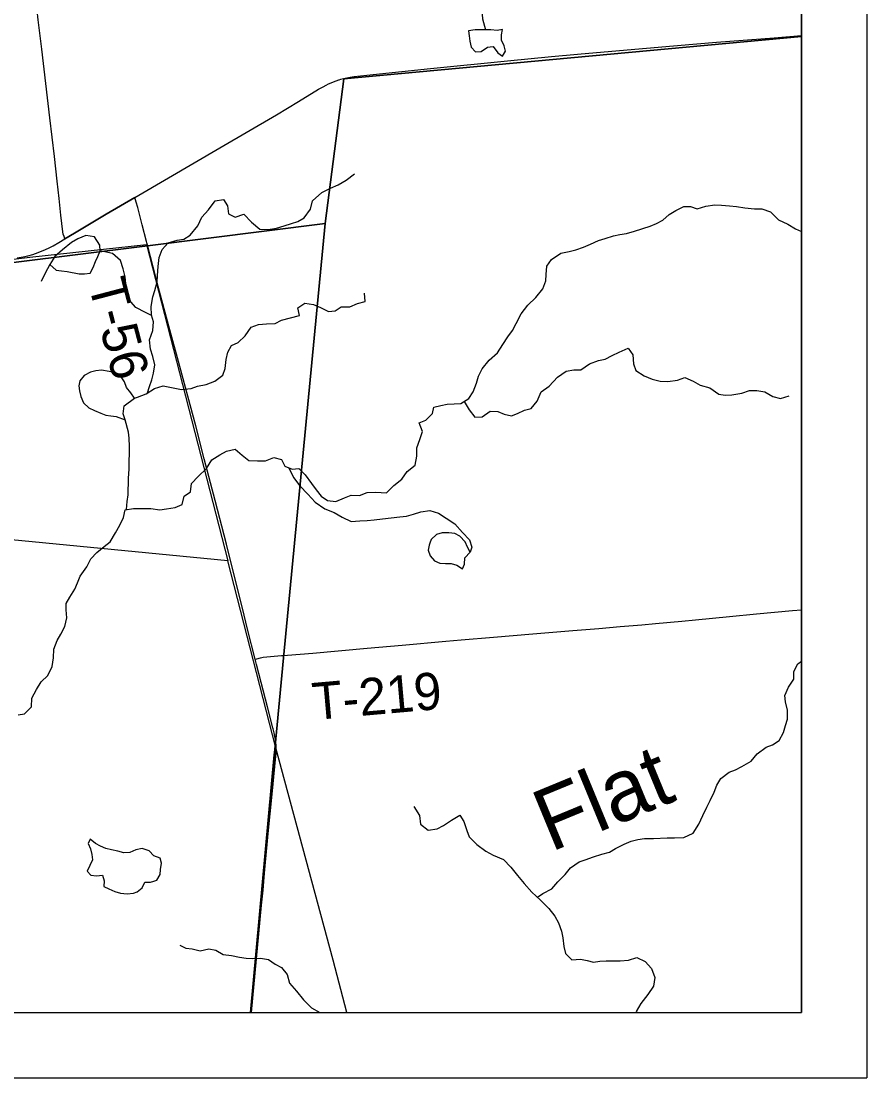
# Model space of a CAD drawing. Extents: x 0 to 34, y -5.4 to 22.
# Drawn here: x 7.705 to 9, y 14 to 15.618 of the extents above; entities that cross this region are included whole.
import ezdxf

# ---------------------------------------------------------------- set-up
doc = ezdxf.new("R2010")
doc.units = 0
for name, color, linetype in [('Default', 7, 'Continuous'), ('GM_X_County_Road', 7, 'Continuous'), ('GM_X_Minor_Lake', 7, 'Continuous'), ('GM_X_Minor_River', 7, 'Continuous'), ('GM_X_Minor_River_Text', 7, 'Continuous'), ('GM_X_Rail_Line', 7, 'Continuous'), ('GM_X_Section', 7, 'Continuous'), ('GM_X_Township_Road', 7, 'Continuous'), ('GM_X_Township_Road_Text', 7, 'Continuous'), ('SH_Data', 7, 'Continuous')]:
    doc.layers.add(name, color=color, linetype=linetype)

msp = doc.modelspace()

# ---------------------------------------------------------------- linework, layer by layer
at = {"layer": 'Default'}
for points in [[(7.0382, 14.1), (8.0569, 14.1), (8.0946, 14.5055), (8.0215, 14.7918), (7.1062, 14.8804)], [(8.0569, 14.1), (8.2036, 14.1), (8.1825, 14.1804), (8.0946, 14.5055)]]:
    msp.add_lwpolyline(points, close=True, dxfattribs=at)
at = {"layer": 'GM_X_County_Road'}
for points in [[(8.1911, 15.528), (8.1917, 15.5282), (8.1946, 15.529), (8.1987, 15.53), (8.2036, 15.5311), (8.2085, 15.5322), (8.215, 15.533), (8.2439, 15.536), (8.3316, 15.5452), (8.4494, 15.5571), (8.5168, 15.5637), (8.5567, 15.5672), (8.633, 15.5742), (8.7334, 15.5828), (8.7695, 15.5856), (8.8581, 15.5925), (8.9, 15.596)], [(7.8787, 15.348), (7.9305, 15.378), (8.0091, 15.4241), (8.096, 15.4745), (8.1296, 15.4946), (8.1604, 15.5136), (8.1674, 15.5175), (8.1717, 15.5199), (8.1755, 15.5218), (8.1795, 15.5236), (8.183, 15.5252), (8.187, 15.5265), (8.1911, 15.528)], [(7.7718, 15.2845), (7.7866, 15.2932), (7.8349, 15.3221), (7.8787, 15.348)], [(7.732, 15.264), (7.7385, 15.2666), (7.7465, 15.2703), (7.7538, 15.2741), (7.7624, 15.2789), (7.7718, 15.2845)], [(7.6989, 15.2557), (7.7077, 15.2571), (7.7152, 15.2586), (7.7228, 15.2607), (7.7307, 15.2635), (7.732, 15.264)]]:
    msp.add_lwpolyline(points, dxfattribs=at)
at = {"layer": 'GM_X_Minor_Lake'}
for points in [[(8.4158, 15.6045), (8.4003, 15.6044), (8.39, 15.603), (8.3907, 15.5954), (8.3921, 15.587), (8.3942, 15.5779), (8.4005, 15.5709), (8.4093, 15.5716), (8.4188, 15.5779), (8.4233, 15.5784)], [(8.4233, 15.5784), (8.4276, 15.5789), (8.435, 15.5696), (8.4418, 15.5642), (8.4464, 15.5717), (8.4443, 15.5801), (8.4406, 15.5889), (8.4404, 15.5969), (8.442, 15.6052), (8.4336, 15.6038), (8.4242, 15.6047), (8.4158, 15.6045)], [(7.8256, 15.266), (7.8254, 15.2751), (7.8169, 15.2874), (7.8041, 15.2895), (7.7915, 15.2848), (7.782, 15.2792), (7.7681, 15.2677), (7.7562, 15.2573), (7.7488, 15.2453)], [(7.7488, 15.2453), (7.7585, 15.2367), (7.7668, 15.2355), (7.7755, 15.2346), (7.7936, 15.2312), (7.8016, 15.2311), (7.8103, 15.2321), (7.815, 15.2408), (7.8185, 15.2498), (7.8224, 15.2577), (7.8256, 15.266)], [(7.8786, 15.0406), (7.8727, 15.0489), (7.8664, 15.057), (7.8631, 15.0654), (7.8568, 15.0746), (7.8478, 15.0801), (7.8395, 15.0817), (7.8277, 15.0834), (7.819, 15.0824), (7.811, 15.0803), (7.8011, 15.0755), (7.7945, 15.0672), (7.7933, 15.0597), (7.7943, 15.0517), (7.796, 15.0433), (7.8004, 15.0334), (7.8087, 15.026), (7.8173, 15.0217), (7.8267, 15.0178), (7.8346, 15.0146), (7.8422, 15.0137), (7.8501, 15.0128), (7.8642, 15.0073)], [(7.8642, 15.0073), (7.8612, 15.0166), (7.8625, 15.0287), (7.8786, 15.0406)], [(8.3923, 14.8047), (8.3882, 14.8127), (8.3849, 14.8207), (8.3767, 14.8292), (8.3688, 14.8335), (8.3597, 14.8344), (8.3495, 14.8342), (8.3408, 14.8317), (8.3327, 14.8242), (8.3307, 14.8187)], [(8.3307, 14.8187), (8.3295, 14.8155), (8.3283, 14.808), (8.3312, 14.7992), (8.3379, 14.7915), (8.3462, 14.7879), (8.3549, 14.7874), (8.3636, 14.7877), (8.3719, 14.7849), (8.3805, 14.7791), (8.384, 14.7866), (8.3842, 14.7961), (8.3923, 14.8047)], [(7.9078, 14.3011), (7.9124, 14.3025), (7.9178, 14.3111), (7.918, 14.3191), (7.92, 14.3285), (7.9175, 14.3365), (7.9081, 14.3397), (7.901, 14.3474), (7.89, 14.351), (7.8802, 14.3489), (7.8714, 14.3452), (7.8619, 14.3446), (7.8528, 14.3471), (7.8434, 14.3491), (7.8343, 14.3511), (7.8264, 14.3547), (7.8189, 14.359), (7.8107, 14.3652), (7.8075, 14.3588), (7.8112, 14.3504), (7.813, 14.342), (7.814, 14.334)], [(7.814, 14.334), (7.8061, 14.3163), (7.8117, 14.3101), (7.8204, 14.3092), (7.8295, 14.3102), (7.8321, 14.3018), (7.8316, 14.2931), (7.8391, 14.2892), (7.8481, 14.2853), (7.8572, 14.2825), (7.8674, 14.2819), (7.8769, 14.2829), (7.8826, 14.2847), (7.8899, 14.2907), (7.8942, 14.2997), (7.9029, 14.2996), (7.9078, 14.3011)]]:
    msp.add_lwpolyline(points, dxfattribs=at)
at = {"layer": 'GM_X_Minor_River'}
for points in [[(8.3922, 15.6544), (8.3989, 15.6438), (8.4104, 15.6341), (8.4113, 15.6212), (8.4158, 15.6045)], [(7.8983, 15.0489), (7.9012, 15.0583), (7.9052, 15.0685), (7.9073, 15.0787), (7.9094, 15.0916), (7.9066, 15.1045), (7.903, 15.1156), (7.9013, 15.13), (7.9065, 15.144), (7.9074, 15.1576), (7.9042, 15.1675), (7.9041, 15.1812), (7.9066, 15.1959), (7.9098, 15.2057), (7.913, 15.2186), (7.9136, 15.2284), (7.9149, 15.2424), (7.9163, 15.2561), (7.921, 15.2681), (7.9299, 15.2786), (7.9436, 15.2825), (7.9542, 15.2843), (7.9638, 15.2902), (7.9754, 15.3044), (7.9817, 15.3179), (7.9917, 15.3291), (8.0018, 15.3426), (8.0147, 15.3447), (8.0209, 15.3351), (8.0226, 15.3229), (8.0324, 15.3178), (8.0457, 15.3221), (8.0576, 15.3102), (8.0703, 15.2993), (8.0831, 15.2987), (8.0957, 15.3008), (8.1078, 15.3044), (8.1189, 15.308), (8.1284, 15.3109), (8.1383, 15.3168), (8.148, 15.3299), (8.1512, 15.3427), (8.1651, 15.3554), (8.1788, 15.3623), (8.1903, 15.3671), (8.2025, 15.3744), (8.2155, 15.3841)], [(8.3367, 15.027), (8.3473, 15.0295), (8.3572, 15.0312), (8.3682, 15.0318), (8.378, 15.0323), (8.3903, 15.0401), (8.3969, 15.0502), (8.402, 15.0634), (8.4052, 15.0744), (8.4107, 15.0853), (8.4215, 15.0987), (8.4342, 15.1099), (8.4427, 15.123), (8.4501, 15.1343), (8.4571, 15.144), (8.463, 15.1549), (8.4708, 15.1696), (8.4808, 15.1831), (8.4928, 15.195), (8.504, 15.2081), (8.5083, 15.2201), (8.5089, 15.23), (8.5098, 15.2425), (8.5172, 15.253), (8.5314, 15.2626), (8.5439, 15.2654), (8.5542, 15.2679), (8.566, 15.2719), (8.5766, 15.2766), (8.5892, 15.2821), (8.5991, 15.2853), (8.612, 15.2893), (8.6215, 15.291), (8.6318, 15.2927), (8.6443, 15.2963), (8.6683, 15.3039), (8.6778, 15.3083), (8.6874, 15.3134), (8.6974, 15.3216), (8.7073, 15.3282), (8.7199, 15.3341), (8.7301, 15.3343), (8.7403, 15.3307), (8.7532, 15.3347), (8.7672, 15.3367), (8.7775, 15.3361), (8.7895, 15.3352), (8.8001, 15.3342), (8.813, 15.3321), (8.8277, 15.3307), (8.839, 15.3305), (8.8526, 15.3261), (8.8649, 15.3138), (8.8788, 15.3071), (8.8908, 15.3001), (8.9, 15.2957)], [(7.9043, 15.1672), (7.8952, 15.1719), (7.8802, 15.1793), (7.8694, 15.1924), (7.8666, 15.2027), (7.8653, 15.2156), (7.8639, 15.2263), (7.8611, 15.2384), (7.8572, 15.2514), (7.8449, 15.2622), (7.8256, 15.266), (7.8254, 15.2751), (7.8169, 15.2874), (7.8041, 15.2895), (7.7915, 15.2848), (7.782, 15.2792), (7.7681, 15.2677), (7.7562, 15.2573), (7.7488, 15.2453), (7.7418, 15.2321), (7.7355, 15.2193)], [(7.8664, 14.8701), (7.8673, 14.8826), (7.8686, 14.8928), (7.869, 14.9178), (7.87, 14.9322), (7.8702, 14.9451), (7.8707, 14.9549), (7.8706, 14.9667), (7.8704, 14.9792), (7.869, 14.9887), (7.8642, 15.0073), (7.8612, 15.0166), (7.8625, 15.0287), (7.8786, 15.0406), (7.8832, 15.042), (7.8961, 15.0474), (7.9088, 15.0556), (7.9221, 15.0595), (7.9353, 15.057), (7.9504, 15.0537), (7.9651, 15.0554), (7.975, 15.059), (7.988, 15.0618), (8.0013, 15.0669), (8.0136, 15.0761), (8.0171, 15.0863), (8.0189, 15.0996), (8.0213, 15.1113), (8.0268, 15.1211), (8.0371, 15.1258), (8.0479, 15.1359), (8.0572, 15.1494), (8.0682, 15.1533), (8.0807, 15.1543), (8.094, 15.1552), (8.1035, 15.1603), (8.1172, 15.1635), (8.1309, 15.1671), (8.1288, 15.1789), (8.1395, 15.1863), (8.1527, 15.1841), (8.1633, 15.1794), (8.1757, 15.1735), (8.1855, 15.1741), (8.1951, 15.1804), (8.2083, 15.1805), (8.2201, 15.1856), (8.2319, 15.1885), (8.2306, 15.2014)], [(8.3832, 15.0356), (8.3907, 15.0226), (8.3996, 15.0115), (8.4106, 15.0121), (8.4229, 15.0206), (8.435, 15.0204), (8.4447, 15.016), (8.4557, 15.0136), (8.4652, 15.0172), (8.4759, 15.0223), (8.4857, 15.0248), (8.495, 15.036), (8.5013, 15.0503), (8.5136, 15.0592), (8.5263, 15.0727), (8.5393, 15.0819), (8.5511, 15.084), (8.5617, 15.0838), (8.5751, 15.0934), (8.5892, 15.0985), (8.599, 15.1002), (8.6097, 15.1061), (8.6204, 15.1113), (8.6345, 15.1171), (8.6415, 15.1071), (8.6424, 15.093), (8.6464, 15.0831), (8.6588, 15.0746), (8.6712, 15.0698), (8.6832, 15.0669), (8.6953, 15.066), (8.7098, 15.0684), (8.7212, 15.0724), (8.734, 15.0668), (8.7448, 15.0606), (8.7595, 15.0565), (8.7734, 15.0468), (8.7832, 15.0451), (8.7934, 15.0457), (8.8086, 15.0481), (8.8204, 15.0524), (8.8313, 15.0523), (8.8438, 15.0501), (8.8558, 15.0431), (8.8678, 15.0399), (8.8812, 15.0442)], [(7.7005, 14.5558), (7.71, 14.5572), (7.7208, 14.568), (7.721, 14.5813), (7.7281, 14.5948), (7.7355, 14.6061), (7.7458, 14.6161), (7.7521, 14.63), (7.7546, 14.6433), (7.7548, 14.6565), (7.76, 14.6697), (7.7658, 14.6795), (7.7717, 14.6912), (7.7746, 14.7044), (7.7736, 14.7165), (7.7738, 14.726), (7.7796, 14.7361), (7.787, 14.7482), (7.791, 14.758), (7.7953, 14.7681), (7.8054, 14.7824), (7.8117, 14.7944), (7.8205, 14.8045), (7.8317, 14.8134), (7.8412, 14.8208), (7.8494, 14.8347), (7.8557, 14.8463), (7.8615, 14.858), (7.864, 14.8697), (7.8769, 14.8718), (7.8898, 14.8716), (7.9034, 14.8717), (7.9174, 14.8696), (7.9276, 14.8713), (7.9409, 14.8733), (7.9516, 14.8777), (7.9544, 14.8905), (7.964, 14.8972), (7.9657, 14.9101), (7.9761, 14.9209), (7.9888, 14.9332), (7.9966, 14.946), (8.0092, 14.9541), (8.0195, 14.9596), (8.0328, 14.9628), (8.0433, 14.9535), (8.0537, 14.9454), (8.067, 14.9448), (8.0791, 14.9449), (8.0917, 14.9496), (8.1033, 14.9468), (8.1085, 14.9365), (8.1201, 14.9321), (8.13, 14.9331), (8.14, 14.923), (8.1497, 14.91), (8.1567, 14.9004), (8.1645, 14.8904), (8.1742, 14.8837), (8.1867, 14.8824), (8.2, 14.8882), (8.2103, 14.8919), (8.2228, 14.8916), (8.2346, 14.8964), (8.2482, 14.8969), (8.2645, 14.8959), (8.2756, 14.9067), (8.2879, 14.9167), (8.296, 14.9283), (8.3083, 14.9383), (8.3108, 14.952), (8.311, 14.9645), (8.3154, 14.9773), (8.3194, 14.9897), (8.3143, 15.0027), (8.3246, 15.0067), (8.3346, 15.0172), (8.3367, 15.027)], [(8.115, 14.934), (8.1218, 14.9192), (8.1318, 14.9065), (8.1437, 14.8938), (8.1552, 14.8814), (8.1698, 14.8713), (8.1841, 14.8654), (8.1965, 14.8583), (8.2104, 14.852), (8.2236, 14.8526), (8.2346, 14.8535), (8.2452, 14.8541), (8.2581, 14.8558), (8.2714, 14.8574), (8.285, 14.8587), (8.2949, 14.8601), (8.3059, 14.8629), (8.3169, 14.8665), (8.3306, 14.8685), (8.3438, 14.8645), (8.3558, 14.8567), (8.3692, 14.8482), (8.3808, 14.8351), (8.3912, 14.8235), (8.3948, 14.8123), (8.3923, 14.8047)], [(8.4954, 14.2766), (8.5035, 14.2823), (8.5177, 14.2896), (8.5265, 14.3001), (8.5377, 14.3113), (8.5462, 14.3217), (8.5592, 14.3306), (8.5687, 14.3339), (8.5813, 14.3386), (8.5942, 14.3425), (8.6056, 14.3457), (8.6152, 14.3513), (8.6285, 14.3579), (8.6388, 14.3622), (8.6491, 14.3651), (8.6597, 14.3664), (8.673, 14.3666), (8.6942, 14.3677), (8.7055, 14.3676), (8.7195, 14.3681), (8.734, 14.3746), (8.7426, 14.3882), (8.7489, 14.4017), (8.7551, 14.4145), (8.7599, 14.4246), (8.7661, 14.4374), (8.7701, 14.448), (8.7763, 14.4581), (8.7893, 14.4678), (8.7989, 14.4714), (8.8084, 14.4765), (8.8226, 14.485), (8.8318, 14.4962), (8.8456, 14.5062), (8.8555, 14.5099), (8.8658, 14.5165), (8.8721, 14.5289), (8.8753, 14.5395), (8.8785, 14.5493), (8.8787, 14.5629), (8.8752, 14.5759), (8.8742, 14.5854), (8.8801, 14.5982), (8.8879, 14.6102), (8.8884, 14.6223), (8.8943, 14.634), (8.9, 14.6378)], [(8.3063, 14.4154), (8.3148, 14.4019), (8.3165, 14.3886), (8.3281, 14.3793), (8.3417, 14.381), (8.3516, 14.3861), (8.3639, 14.3946), (8.3765, 14.402), (8.3828, 14.3924), (8.3875, 14.3787), (8.3907, 14.3692), (8.4026, 14.3572), (8.4164, 14.3471), (8.4277, 14.3408), (8.4435, 14.3341), (8.455, 14.3225), (8.465, 14.3099), (8.4754, 14.2975), (8.4869, 14.2844), (8.5003, 14.2721), (8.513, 14.2593), (8.5222, 14.2474), (8.5277, 14.2371), (8.5325, 14.2245), (8.5342, 14.2146), (8.5358, 14.2009), (8.5383, 14.1903), (8.5484, 14.1806), (8.5613, 14.1819), (8.5714, 14.1798), (8.5812, 14.177), (8.5911, 14.1787), (8.6009, 14.1793), (8.6221, 14.179), (8.635, 14.1803), (8.6476, 14.1842), (8.6607, 14.1783), (8.67, 14.1672), (8.6754, 14.1538), (8.6733, 14.1405), (8.6644, 14.1274), (8.6536, 14.114), (8.6466, 14.1016), (8.6477, 14.1)], [(7.9476, 14.2031), (7.9568, 14.1987), (7.9666, 14.1974), (7.979, 14.1942), (7.9923, 14.1974), (8.0029, 14.1957), (8.0141, 14.1886), (8.027, 14.1873), (8.0394, 14.1848), (8.0492, 14.1831), (8.0591, 14.1829), (8.0712, 14.1831), (8.0837, 14.181), (8.0938, 14.174), (8.1035, 14.1689), (8.1124, 14.1581), (8.116, 14.1448), (8.1267, 14.1329), (8.1371, 14.1194), (8.1494, 14.1071), (8.1623, 14.1)]]:
    msp.add_lwpolyline(points, dxfattribs=at)
at = {"layer": 'GM_X_Rail_Line'}
msp.add_lwpolyline([(4.0439, 14.8538), (4.7395, 14.9295), (4.8765, 14.9444), (6.1164, 15.0793), (6.4403, 15.1171), (6.4463, 15.1177), (6.92, 15.1674), (6.9294, 15.1684), (6.9348, 15.169), (6.9914, 15.1749), (7.0389, 15.1799), (7.3134, 15.2082), (7.6796, 15.247), (7.6929, 15.2483), (7.8942, 15.2734), (7.8983, 15.2739), (8.1702, 15.3079), (8.1991, 15.5295), (8.9, 15.5944), (8.9, 19.2127)], dxfattribs=at)
for points in [[(8.0559, 14.1), (8.9, 14.1), (8.9, 15.5944), (8.1991, 15.5295), (8.1702, 15.3079), (8.1066, 14.6429), (8.0933, 14.5029), (8.0925, 14.4946)], [(2.9527, 14.1), (8.0559, 14.1), (8.0925, 14.4946), (8.0933, 14.5029), (8.1066, 14.6429), (8.1702, 15.3079), (7.8983, 15.2739), (7.8942, 15.2734), (7.6929, 15.2483), (7.6796, 15.247), (7.3134, 15.2082), (7.0389, 15.1799), (6.9914, 15.1749), (6.9348, 15.169), (6.9294, 15.1684), (6.92, 15.1674), (6.4463, 15.1177), (6.4403, 15.1171), (6.1164, 15.0793), (4.8765, 14.9444), (4.7395, 14.9295), (4.0439, 14.8538), (3.0059, 14.7462), (2.9641, 14.2324)]]:
    msp.add_lwpolyline(points, close=True, dxfattribs=at)
at = {"layer": 'GM_X_Section'}
msp.add_lwpolyline([(7.7181, 15.2564), (7.8967, 15.2761), (8.0215, 14.7918), (7.1062, 14.8804), (7.1421, 15.1859)], close=True, dxfattribs=at)
at = {"layer": 'GM_X_Township_Road'}
for p, q in [((7.8974, 15.2786), (7.8969, 15.2805)), ((8.1065, 14.6467), (8.1125, 14.6472))]:
    msp.add_line(p, q, dxfattribs=at)
for points in [[(7.7718, 15.2845), (7.7706, 15.2881), (7.7693, 15.2918), (7.7686, 15.2952), (7.7658, 15.321), (7.763, 15.3464), (7.7601, 15.3729), (7.7558, 15.4106), (7.7489, 15.4699), (7.7366, 15.575), (7.7311, 15.6198), (7.7294, 15.6344), (7.728, 15.6469), (7.7268, 15.6591), (7.7258, 15.6691), (7.7214, 15.707), (7.7198, 15.722)], [(7.8787, 15.348), (7.8349, 15.3221), (7.7866, 15.2932), (7.7718, 15.2845)], [(7.8969, 15.2805), (7.8902, 15.3062), (7.8834, 15.3326), (7.8809, 15.3409), (7.8787, 15.348)], [(8.0903, 14.5359), (8.0819, 14.5681), (8.0724, 14.6055), (8.0654, 14.6326), (8.0633, 14.6409), (8.0517, 14.6868), (8.0438, 14.7193), (8.0267, 14.7881), (8.0193, 14.8169), (8.0019, 14.8837), (7.985, 14.9477), (7.9721, 14.9985), (7.9441, 15.1023), (7.9324, 15.1455), (7.9146, 15.2114), (7.8988, 15.273), (7.8974, 15.2786)], [(8.1125, 14.6472), (8.1515, 14.6504), (8.2346, 14.658), (8.2884, 14.6626), (8.3552, 14.6684), (8.3789, 14.6706), (8.4281, 14.6748), (8.4886, 14.6799), (8.5497, 14.685), (8.5897, 14.6881), (8.6224, 14.6908), (8.6553, 14.6937), (8.6764, 14.6955), (8.7165, 14.6994), (8.7375, 14.7013), (8.7898, 14.7063), (8.831, 14.7104), (8.8863, 14.7154), (8.9, 14.7168)], [(8.0633, 14.6409), (8.0656, 14.6415), (8.0714, 14.6431), (8.0756, 14.6439), (8.081, 14.6446), (8.1035, 14.6464), (8.1065, 14.6467)], [(8.0933, 14.4767), (8.0952, 14.4973), (8.0954, 14.502), (8.0954, 14.5053), (8.0953, 14.5096), (8.0949, 14.5133), (8.0942, 14.5182), (8.0935, 14.5224), (8.0921, 14.5282), (8.0907, 14.5345), (8.0903, 14.5359)], [(8.0572, 14.1), (8.0613, 14.1426), (8.0669, 14.2025), (8.0705, 14.2409), (8.0752, 14.2872), (8.0787, 14.3267), (8.0833, 14.3739), (8.0893, 14.4343), (8.0933, 14.4767)]]:
    msp.add_lwpolyline(points, dxfattribs=at)
at = {"layer": 'SH_Data'}
for p, q in [((9, 21), (9, 14)), ((8.9, 20.9), (8.9, 14.1)), ((2.1, 14.1), (8.9, 14.1)), ((2, 14), (9, 14))]:
    msp.add_line(p, q, dxfattribs=at)

# ---------------------------------------------------------------- texts
at = {"layer": 'GM_X_Minor_River_Text'}
msp.add_text('Flat', height=0.0947, rotation=22.4359, dxfattribs=at).set_placement((8.5156, 14.3452))
at = {"layer": 'GM_X_Township_Road_Text'}
for s, rotation, p in [('T-56', 284.7254, (7.8073, 15.2159)), ('T-219', 5.0428, (8.153, 14.5477))]:
    msp.add_text(s, height=0.05682, rotation=rotation, dxfattribs=at).set_placement(p)

doc.saveas('drawing.dxf')
